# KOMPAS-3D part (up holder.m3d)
File: created 05.10.2016 12:08:21, last saved 05.10.2016 12:10:10.
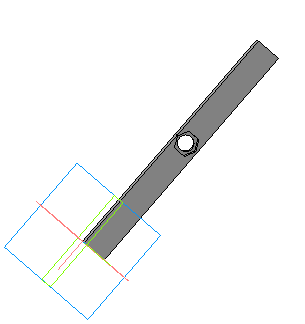
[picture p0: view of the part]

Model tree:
1. Эскиз:1
2. Операция выдавливания:1
     Расстояние 1 = 10
3. Эскиз:2
4. Вырезать элемент выдавливания:1
     Расстояние 1 = 6
5. Эскиз:3
6. Вырезать элемент выдавливания:2
     Расстояние 1 = 6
